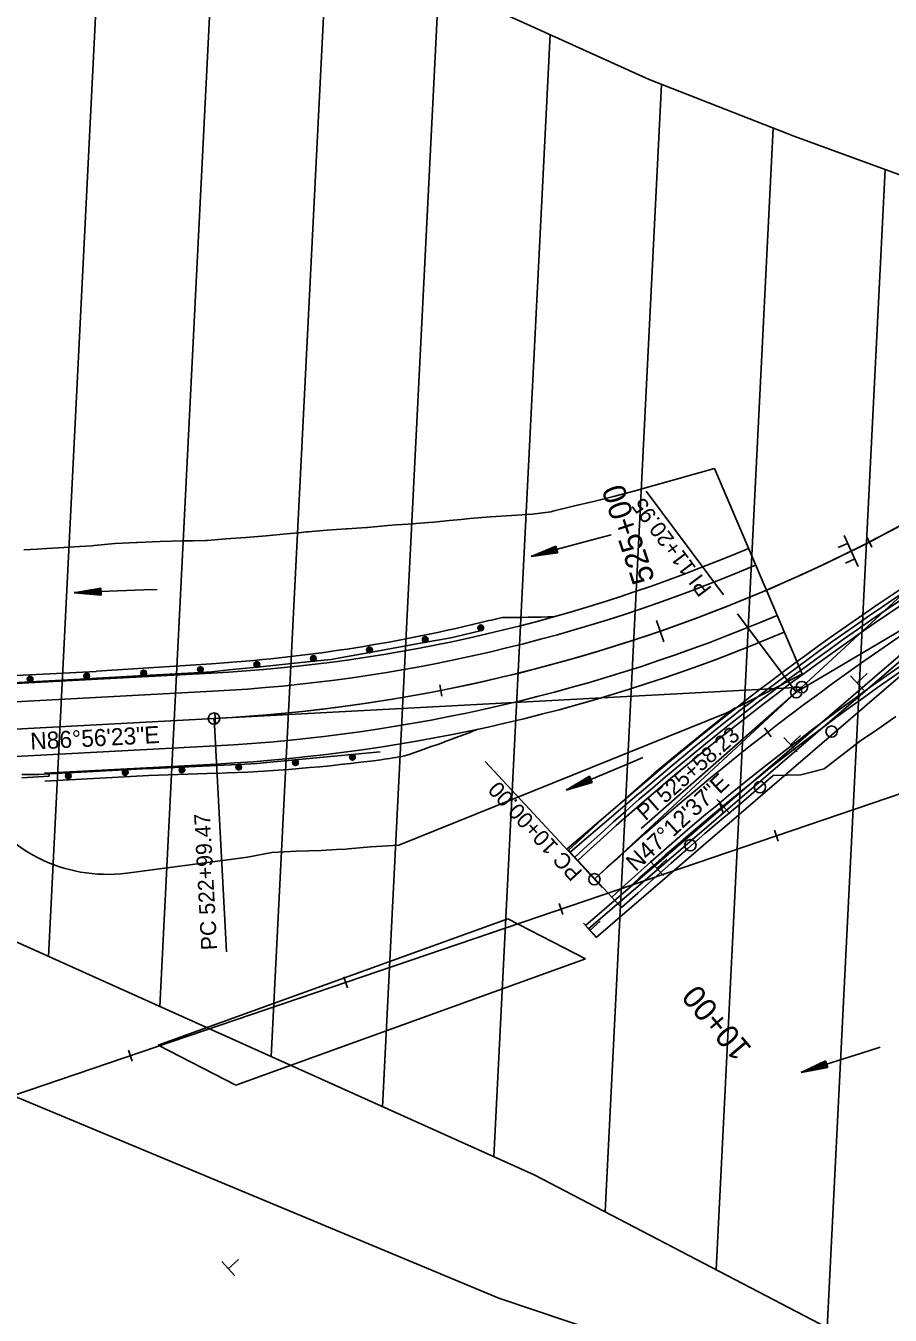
# Model space of a CAD drawing. Extents: x 1300404 to 1323571, y 234004 to 252077.
# Drawn here: x 1310836 to 1311216, y 241590 to 242157 of the extents above; entities that cross this region are included whole.
import ezdxf

# ---------------------------------------------------------------- set-up
doc = ezdxf.new("R2010")
doc.units = 0
for name, color, linetype in [('MOT Stage 1', 7, 'Continuous'), ('R_Barrel', 7, 'Continuous'), ('R_Bridge', 7, 'Continuous'), ('R_BRIDGE OLD', 7, 'Continuous'), ('R_Const Limits', 7, 'Continuous'), ('R_Floodway', 7, 'Continuous'), ('R_Flooplain', 7, 'Continuous'), ('R_Flow Arrows', 7, 'Continuous'), ('R_Guardrail', 7, 'Continuous'), ('R_Horz Alg Annot', 7, 'Continuous'), ('R_Horz Alg Annot Leader', 7, 'Continuous'), ('R_Horz Alg Major Ticks', 7, 'Continuous'), ('R_Horz Alg Minor Ticks', 7, 'Continuous'), ('R_Horz Alg Station Annot', 7, 'Continuous'), ('R_Horz Alg Tangents', 7, 'Continuous'), ('R_Horz Alg Tangents Text', 7, 'Continuous'), ('R_Lane Edge', 7, 'Continuous'), ('R_MOT Proposed', 7, 'Continuous'), ('R_No Plot', 7, 'Continuous'), ('R_Proposed', 7, 'Continuous'), ('R_Shoulder', 7, 'Continuous'), ('R_Temp Widening', 7, 'Continuous')]:
    doc.layers.add(name, color=color, linetype=linetype)

msp = doc.modelspace()

# ---------------------------------------------------------------- linework, layer by layer
at = {"layer": 'MOT Stage 1'}
for p, q in [((1311201.61, 241919.34), (1311195.34, 241932.97)), ((1311196.91, 241929.57), (1311192.82, 241927.69)), ((1311200.04, 241922.75), (1311195.95, 241920.87))]:
    msp.add_line(p, q, dxfattribs=at)
at = {"layer": 'R_Barrel'}
for p, q in [((1311204.01, 241865.09), (1311198.16, 241871.4)), ((1311201.1, 241868.23), (1311205.5, 241872.31)), ((1311174.67, 241837.91), (1311168.82, 241844.22)), ((1311171.76, 241841.05), (1311176.16, 241845.13)), ((1311142.41, 241813.87), (1311146.81, 241817.95)), ((1311145.32, 241810.73), (1311139.47, 241817.04)), ((1311115.97, 241783.55), (1311110.12, 241789.86)), ((1311113.06, 241786.69), (1311117.46, 241790.77)), ((1311086.63, 241756.37), (1311080.78, 241762.68)), ((1311083.72, 241759.51), (1311088.12, 241763.58)), ((1310927.51, 241607.6), (1310921.8, 241614.04)), ((1310924.67, 241610.81), (1310929.16, 241614.78))]:
    msp.add_line(p, q, dxfattribs=at)
at = {"layer": 'R_Bridge'}
for p, q in [((1310841.4, 241827.99), (1310833.89, 241828.01)), ((1310833.97, 241826.59), (1310845.95, 241827.23)), ((1310845.9, 241828.23), (1310841.4, 241827.99)), ((1310845.95, 241827.23), (1310845.9, 241828.23))]:
    msp.add_line(p, q, dxfattribs=at)
at = {"layer": 'R_BRIDGE OLD'}
for p, q in [((1310893.84, 241709.07), (1311047.62, 241764.63)), ((1311047.62, 241764.63), (1311081.7, 241747.01)), ((1310927.92, 241691.44), (1311081.7, 241747.01)), ((1310893.84, 241709.07), (1310927.92, 241691.44))]:
    msp.add_line(p, q, dxfattribs=at)
at = {"layer": 'R_Const Limits'}
for p, q in [((1311176.88, 241872.18), (1311138.36, 241962.48)), ((1311086.31, 241756.33), (1311264.65, 241909.6)), ((1311086.31, 241756.33), (1311081.74, 241761.64))]:
    msp.add_line(p, q, dxfattribs=at)
for points in [[(1310834.85, 241926.68), (1310840.61, 241926.98), (1310844.84, 241927.26), (1310854.81, 241927.93), (1310859.32, 241928.23), (1310864.8, 241928.45), (1310865.67, 241928.55), (1310874.76, 241929.47), (1310884.27, 241929.9), (1310884.75, 241929.92), (1310894.74, 241930.32), (1310904.74, 241930.67), (1310909.26, 241930.74), (1310914.69, 241930.86), (1310915.46, 241930.89), (1310923.57, 241931.5), (1310932.44, 241932.19), (1310941.32, 241932.89), (1310950.19, 241933.75), (1310955.64, 241934.26), (1310959.05, 241934.6), (1310959.83, 241934.67), (1310967.95, 241935.3), (1310976.44, 241935.95), (1310976.86, 241935.99), (1310985.38, 241936.54), (1310985.81, 241936.58), (1310994.75, 241937.37), (1310998.54, 241937.7), (1311003.75, 241937.97), (1311012.75, 241938.72), (1311015.02, 241938.93), (1311021.76, 241939.54), (1311027.06, 241940.05), (1311030.8, 241940.43), (1311036.1, 241941), (1311039.91, 241941.15), (1311049.1, 241941.74), (1311058.31, 241942.46), (1311066.41, 241943.48), (1311067.39, 241943.76), (1311076.26, 241945.88), (1311085.19, 241947.89), (1311094.05, 241950.15), (1311102.88, 241952.57), (1311111.72, 241955.02), (1311120.61, 241957.41), (1311129.48, 241959.91), (1311138.36, 241962.48), (1311138.36, 241962.48)], [(1311176.88, 241872.18), (1311176.88, 241872.18), (1311167.49, 241867.24), (1311158.01, 241862.48), (1311148.53, 241857.62), (1311143.8, 241855.03)], [(1311143.8, 241855.03), (1310999.61, 241796.95)], [(1310999.61, 241796.95), (1310999.61, 241796.95), (1310987.26, 241796.18), (1310977.37, 241795.28), (1310976.42, 241795.2), (1310972.24, 241794.96), (1310965.56, 241794.59), (1310954.67, 241794.33), (1310943.84, 241793.72), (1310933.11, 241791.68), (1310923.25, 241790.38), (1310880.01, 241784.67), (1310880.01, 241784.67)]]:
    msp.add_lwpolyline(points, dxfattribs=at)
msp.add_arc((1310871.29, 241850.65), 66.55, 208.0604, 277.5275, dxfattribs=at)
at = {"layer": 'R_Floodway'}
for p, q in [((1310845.63, 241748), (1310870.89, 242252.19)), ((1310894.59, 241726), (1310919.58, 242224.73)), ((1310943.55, 241703.99), (1310968.37, 242199.27)), ((1310992.51, 241681.98), (1311017.25, 242175.67)), ((1311041.47, 241659.98), (1311066.18, 242153.15)), ((1311090.32, 241635.77), (1311115.15, 242131.3)), ((1311139.11, 241610.32), (1311164.25, 242112.14)), ((1311187.9, 241584.88), (1311213.4, 242093.9))]:
    msp.add_line(p, q, dxfattribs=at)
for points in [[(1312749.18, 241191.87), (1312719.26, 241174.03), (1312375.34, 241167.16), (1311696.89, 241341.68), (1311497.53, 241419.47), (1311333.82, 241508.77), (1311059.08, 241652.06), (1310740.78, 241795.13), (1310453.25, 241924.55), (1310367.2, 241994.21), (1310267.81, 242111.73), (1309996.24, 242391.57), (1309869.69, 242546.75), (1309624.53, 242919.62)], [(1310244.92, 242890.78), (1310303.34, 242800.73), (1310379.63, 242680.75), (1310490.18, 242568.72), (1310548.96, 242534.3), (1310676.05, 242414.18), (1310731.56, 242362.99), (1310810.26, 242291.28), (1310887.62, 242241.41), (1310974.87, 242195.88), (1311031.59, 242168.82), (1311109.67, 242133.43), (1311173.76, 242108.43), (1311242.66, 242083.18), (1311339.33, 242032.34), (1311351.04, 242024.49), (1311431.54, 241940.59), (1311405.15, 241750.77), (1311416.02, 241677.63), (1311441.14, 241598.94), (1311547.83, 241506.46)]]:
    msp.add_lwpolyline(points, dxfattribs=at)
at = {"layer": 'R_Flooplain'}
msp.add_lwpolyline([(1308850.44, 242983.42), (1308921.9, 242863.68), (1309009.78, 242685.04), (1309044.07, 242596.21), (1309055.9, 242542.38), (1309352.07, 242367.77), (1309503.16, 242292.41), (1309669.46, 242230.8), (1309815.49, 242150.85), (1309936.66, 242057.64), (1310419.39, 241839.75), (1310733.16, 241727.16), (1311043.67, 241597.79), (1311103.17, 241577.86), (1311152.77, 241553.58), (1311178, 241525.7), (1311328.48, 241486.66), (1311553.07, 241380.98), (1311870.34, 241289.99), (1312137.52, 241213.62), (1312460.11, 241035.25), (1312721.15, 240884.18), (1312883.23, 240786.49)], dxfattribs=at)
at = {"layer": 'R_Flow Arrows'}
for p, q in [((1311068.69, 241928.4), (1311057.77, 241923.79)), ((1311069.5, 241925.47), (1311057.77, 241923.79)), ((1311069.5, 241925.47), (1311068.69, 241928.4)), ((1310868.58, 241909.89), (1310856.91, 241907.82)), ((1310868.72, 241906.86), (1310868.58, 241909.89)), ((1310868.72, 241906.86), (1310856.91, 241907.82)), ((1311083.45, 241827.21), (1311073.26, 241821.16)), ((1311084.65, 241824.42), (1311073.26, 241821.16)), ((1311084.65, 241824.42), (1311083.45, 241827.21)), ((1311187.21, 241702.12), (1311176.51, 241697.03)), ((1311188.15, 241699.23), (1311176.51, 241697.03)), ((1311188.15, 241699.23), (1311187.21, 241702.12))]:
    msp.add_line(p, q, dxfattribs=at)
for points in [[(1311092.99, 241933.34), (1311087.43, 241931.84), (1311057.74, 241923.93)], [(1311069.01, 241927.22), (1311063.02, 241925.56), (1311059.96, 241924.72)], [(1311069.18, 241926.64), (1311063.19, 241924.98), (1311060.12, 241924.13)], [(1311068.93, 241927.52), (1311062.94, 241925.86), (1311062.14, 241925.64)], [(1311069.26, 241926.35), (1311063.27, 241924.68), (1311062.46, 241924.46)], [(1311068.85, 241927.81), (1311064.32, 241926.55)], [(1311069.34, 241926.05), (1311064.81, 241924.8)], [(1311068.77, 241928.1), (1311066.51, 241927.48)], [(1311069.42, 241925.76), (1311067.16, 241925.13)], [(1310893.37, 241909.32), (1310887.61, 241909.09), (1310856.9, 241907.97)], [(1310868.63, 241908.68), (1310862.42, 241908.39), (1310859.24, 241908.25)], [(1310868.66, 241908.07), (1310862.45, 241907.78), (1310859.27, 241907.64)], [(1310868.62, 241908.98), (1310862.41, 241908.69), (1310861.58, 241908.65)], [(1310868.6, 241909.29), (1310863.91, 241909.07)], [(1310868.59, 241909.59), (1310866.24, 241909.48)], [(1310868.68, 241907.77), (1310862.46, 241907.48), (1310861.63, 241907.44)], [(1310868.69, 241907.46), (1310863.99, 241907.24)], [(1310868.7, 241907.16), (1310866.36, 241907.05)], [(1311106.85, 241835.41), (1311101.54, 241833.17), (1311073.2, 241821.3)], [(1311083.93, 241826.09), (1311078.22, 241823.63), (1311075.29, 241822.38)], [(1311084.17, 241825.53), (1311078.46, 241823.07), (1311075.53, 241821.82)], [(1311083.81, 241826.37), (1311078.1, 241823.91), (1311077.33, 241823.58)], [(1311084.29, 241825.25), (1311078.58, 241822.79), (1311077.81, 241822.46)], [(1311083.69, 241826.65), (1311079.37, 241824.79)], [(1311084.41, 241824.98), (1311080.09, 241823.11)], [(1311083.57, 241826.93), (1311081.41, 241826)], [(1311084.53, 241824.7), (1311082.37, 241823.77)], [(1311211.27, 241708.14), (1311205.77, 241706.39), (1311176.46, 241697.17)], [(1311187.58, 241700.96), (1311181.67, 241699.04), (1311178.65, 241698.06)], [(1311187.77, 241700.39), (1311181.86, 241698.46), (1311178.83, 241697.48)], [(1311187.49, 241701.25), (1311181.58, 241699.33), (1311180.79, 241699.07)], [(1311187.87, 241700.1), (1311181.95, 241698.17), (1311181.16, 241697.91)], [(1311187.39, 241701.54), (1311182.93, 241700.08)], [(1311187.96, 241699.81), (1311183.49, 241698.35)], [(1311187.3, 241701.83), (1311185.07, 241701.1)], [(1311188.05, 241699.52), (1311185.82, 241698.79)]]:
    msp.add_lwpolyline(points, dxfattribs=at)
at = {"layer": 'R_Guardrail'}
for p, q in [((1311036.38, 241891.45), (1311034.42, 241892.42)), ((1311011.98, 241886.29), (1311010.01, 241887.25)), ((1310987.47, 241881.74), (1310985.5, 241882.7)), ((1310913.11, 241873.04), (1310911.14, 241874.01)), ((1310937.94, 241875.32), (1310935.97, 241876.29)), ((1310962.78, 241877.96), (1310960.81, 241878.93)), ((1310838.28, 241868.8), (1310836.32, 241869.77)), ((1310863.15, 241870.24), (1310861.18, 241871.21)), ((1310888.19, 241871.56), (1310886.22, 241872.53)), ((1310979.96, 241834.54), (1310977.99, 241835.51)), ((1310880.1, 241827.78), (1310878.14, 241828.75)), ((1310905.03, 241829.04), (1310903.06, 241830)), ((1310929.97, 241830.25), (1310928, 241831.21)), ((1310954.92, 241832.17), (1310952.95, 241833.14)), ((1310855.07, 241826.39), (1310853.11, 241827.36))]:
    msp.add_line(p, q, dxfattribs=at)
for points in [[(1311023.77, 241888.41), (1311035.95, 241891.24)], [(1311036.73, 241891.83), (1311034.51, 241892.92)], [(1311035.67, 241891.21), (1311034.66, 241891.71)], [(1311036.89, 241892.31), (1311034.79, 241893.34)], [(1311036.85, 241892.87), (1311035.26, 241893.66)], [(1311035.95, 241891.24), (1311036.51, 241891.37)], [(1310986.89, 241881.64), (1311011.49, 241886.09)], [(1311012.33, 241886.67), (1311010.1, 241887.76)], [(1311011.27, 241886.04), (1311010.25, 241886.54)], [(1311012.48, 241887.14), (1311010.39, 241888.17)], [(1311012.44, 241887.71), (1311010.86, 241888.49)], [(1311011.49, 241886.09), (1311021.72, 241887.94), (1311023.77, 241888.41)], [(1310963.28, 241878.82), (1310961.19, 241879.85)], [(1310963.25, 241879.39), (1310961.66, 241880.17)], [(1310974.59, 241879.41), (1310986.89, 241881.64)], [(1310987.81, 241882.12), (1310985.59, 241883.21)], [(1310986.76, 241881.49), (1310985.74, 241881.99)], [(1310987.97, 241882.59), (1310985.88, 241883.62)], [(1310987.93, 241883.16), (1310986.35, 241883.94)], [(1310913.45, 241873.43), (1310911.23, 241874.52)], [(1310913.61, 241873.9), (1310911.51, 241874.93)], [(1310913.57, 241874.47), (1310911.99, 241875.25)], [(1310912.46, 241872.85), (1310917.47, 241873.14), (1310924.91, 241873.91)], [(1310924.91, 241873.91), (1310937.34, 241875.19)], [(1310938.28, 241875.7), (1310936.06, 241876.79)], [(1310937.23, 241875.08), (1310936.21, 241875.58)], [(1310938.44, 241876.18), (1310936.35, 241877.21)], [(1310938.4, 241876.74), (1310936.82, 241877.53)], [(1310937.34, 241875.19), (1310962.21, 241877.76)], [(1310963.13, 241878.35), (1310960.9, 241879.44)], [(1310962.07, 241877.72), (1310961.06, 241878.22)], [(1310962.21, 241877.76), (1310969.88, 241878.56), (1310974.59, 241879.41)], [(1310825.09, 241868.03), (1310837.57, 241868.7)], [(1310838.63, 241869.18), (1310836.41, 241870.28)], [(1310837.57, 241868.56), (1310836.56, 241869.06)], [(1310838.78, 241869.66), (1310836.69, 241870.69)], [(1310838.75, 241870.23), (1310837.16, 241871.01)], [(1310837.57, 241868.7), (1310862.54, 241870.03)], [(1310863.5, 241870.63), (1310861.28, 241871.72)], [(1310862.44, 241870), (1310861.43, 241870.5)], [(1310863.65, 241871.1), (1310861.56, 241872.13)], [(1310863.62, 241871.67), (1310862.03, 241872.45)], [(1310862.54, 241870.03), (1310866.78, 241870.26), (1310875.02, 241870.73)], [(1310875.02, 241870.73), (1310887.5, 241871.44)], [(1310888.53, 241871.95), (1310886.31, 241873.04)], [(1310887.48, 241871.32), (1310886.46, 241871.82)], [(1310888.69, 241872.42), (1310886.59, 241873.45)], [(1310888.65, 241872.99), (1310887.06, 241873.77)], [(1310887.5, 241871.44), (1310912.46, 241872.85)], [(1310912.4, 241872.8), (1310911.38, 241873.3)], [(1310954.11, 241834.41), (1310941.66, 241833.23)], [(1310955.39, 241833.59), (1310953.8, 241834.38)], [(1310978.99, 241836.78), (1310954.11, 241834.41)], [(1310980.3, 241834.92), (1310978.08, 241836.02)], [(1310979.25, 241834.3), (1310978.23, 241834.8)], [(1310980.46, 241835.4), (1310978.36, 241836.43)], [(1310980.42, 241835.97), (1310978.84, 241836.75)], [(1310991.44, 241837.97), (1310978.99, 241836.78)], [(1310854.28, 241828.68), (1310845.9, 241828.23)], [(1310855.54, 241827.82), (1310853.95, 241828.6)], [(1310879.25, 241830.01), (1310854.28, 241828.68)], [(1310880.45, 241828.16), (1310878.23, 241829.26)], [(1310880.61, 241828.64), (1310878.51, 241829.67)], [(1310880.57, 241829.21), (1310878.98, 241829.99)], [(1310891.73, 241830.67), (1310889.6, 241830.57), (1310889.58, 241830.57), (1310879.25, 241830.01)], [(1310904.22, 241831.27), (1310891.73, 241830.67)], [(1310905.37, 241829.42), (1310903.15, 241830.51)], [(1310904.32, 241828.79), (1310903.3, 241829.29)], [(1310905.53, 241829.89), (1310903.44, 241830.92)], [(1310905.49, 241830.46), (1310903.91, 241831.24)], [(1310929.19, 241832.44), (1310919.51, 241832), (1310904.22, 241831.27)], [(1310930.32, 241830.63), (1310928.09, 241831.72)], [(1310929.26, 241830), (1310928.24, 241830.5)], [(1310930.47, 241831.1), (1310928.38, 241832.13)], [(1310930.43, 241831.67), (1310928.85, 241832.45)], [(1310941.66, 241833.23), (1310937.35, 241832.82), (1310929.19, 241832.44)], [(1310955.27, 241832.55), (1310953.05, 241833.64)], [(1310954.21, 241831.93), (1310953.2, 241832.43)], [(1310955.42, 241833.03), (1310953.33, 241834.06)], [(1310855.42, 241826.77), (1310853.2, 241827.87)], [(1310854.37, 241826.15), (1310853.35, 241826.65)], [(1310855.58, 241827.25), (1310853.48, 241828.28)], [(1310879.4, 241827.54), (1310878.38, 241828.04)]]:
    msp.add_lwpolyline(points, dxfattribs=at)
for centre in [(1311035.67, 241892.47), (1311011.26, 241887.31), (1310962.06, 241878.99), (1310986.75, 241882.76), (1310912.39, 241874.07), (1310937.22, 241876.34), (1310837.57, 241869.83), (1310862.43, 241871.27), (1310887.47, 241872.59), (1310954.2, 241833.19), (1310979.24, 241835.56), (1310854.36, 241827.42), (1310879.39, 241828.8), (1310904.31, 241830.06), (1310929.25, 241831.27)]:
    msp.add_circle(centre, 1.25, dxfattribs=at)
at = {"layer": 'R_Horz Alg Annot Leader'}
for points in [[(1311176.79, 241866.37), (1311106.14, 241804.2)], [(1311176.79, 241866.37), (1311106.14, 241804.2)], [(1310918.4, 241852.55), (1310923.88, 241750.03)], [(1310918.4, 241852.55), (1310923.88, 241750.03)]]:
    msp.add_lwpolyline(points, dxfattribs=at)
at = {"layer": 'R_Horz Alg Major Ticks'}
msp.add_lwpolyline([(1311112.91, 241895.7), (1311116.18, 241886.25)], dxfattribs=at)
msp.add_lwpolyline([(1311112.91, 241895.7), (1311116.18, 241886.25)], dxfattribs=at)
at = {"layer": 'R_Horz Alg Minor Ticks'}
for points in [[(1311205.31, 241932.4), (1311207.59, 241927.95)], [(1311205.31, 241932.4), (1311207.59, 241927.95)], [(1311017.6, 241867.39), (1311018.56, 241862.48)], [(1311017.6, 241867.39), (1311018.56, 241862.48)], [(1310918.79, 241855.08), (1310919.06, 241850.09)], [(1310918.79, 241855.08), (1310919.06, 241850.09)], [(1311164.81, 241803.47), (1311166.43, 241798.74)], [(1311164.81, 241803.47), (1311166.43, 241798.74)], [(1311070.15, 241771.25), (1311071.76, 241766.52)], [(1311070.15, 241771.25), (1311071.76, 241766.52)], [(1310975.48, 241739.02), (1310977.09, 241734.29)], [(1310975.48, 241739.02), (1310977.09, 241734.29)], [(1310880.82, 241706.8), (1310882.43, 241702.07)], [(1310880.82, 241706.8), (1310882.43, 241702.07)]]:
    msp.add_lwpolyline(points, dxfattribs=at)
at = {"layer": 'R_Horz Alg Tangents'}
for p, q in [((1311176.79, 241866.37), (1311366.68, 242042.15)), ((1311176.79, 241866.37), (1311366.68, 242042.15)), ((1310918.4, 241852.55), (1311176.79, 241866.37)), ((1310918.4, 241852.55), (1311176.79, 241866.37))]:
    msp.add_line(p, q, dxfattribs=at)
at = {"layer": 'R_Lane Edge'}
for p, q in [((1310472.71, 241840.74), (1310917.76, 241864.54)), ((1310533.26, 241819.95), (1310919.04, 241840.57))]:
    msp.add_line(p, q, dxfattribs=at)
for radius in [704.2, 728.2]:
    msp.add_arc((1310880.16, 242567.73), radius, 273.06037, 293.10284, dxfattribs=at)
at = {"layer": 'R_MOT Proposed'}
for p, q in [((1311174.35, 241864.11), (1311278.31, 241925.93)), ((1311085.59, 241781.94), (1311174.35, 241864.11))]:
    msp.add_line(p, q, dxfattribs=at)
for points in [[(1311142.37, 241906.91), (1311108.3, 241952.5)], [(1311174.35, 241864.11), (1311148.56, 241898.62)], [(1311160.31, 241848.56), (1311163.37, 241844.61)], [(1311085.59, 241781.94), (1311037.61, 241833.77)], [(1311082.19, 241785.61), (1311088.98, 241778.27)]]:
    msp.add_lwpolyline(points, dxfattribs=at)
for centre in [(1311174.35, 241864.11), (1311085.59, 241781.94)]:
    msp.add_circle(centre, 2.5, dxfattribs=at)
msp.add_arc((1311864.02, 240941.01), 1145.92, 120.73904, 132.78965, dxfattribs=at)
at = {"layer": 'R_No Plot'}
for p, q in [((1311103.85, 241821.08), (1311073.6, 241795.35)), ((1311105.21, 241819.61), (1311074.95, 241793.89)), ((1311140.42, 241816.28), (1311142.25, 241811))]:
    msp.add_line(p, q, dxfattribs=at)
msp.add_lwpolyline([(1311218.17, 241853.52), (1311210.21, 241847.87), (1311202.11, 241842.43), (1311194.35, 241836.51), (1311186.65, 241830.52), (1311176.34, 241827.89), (1311164.14, 241827.53), (1311156.65, 241821.12), (1311149.2, 241814.66), (1311141.57, 241808.43), (1311134.11, 241802), (1311126.7, 241795.51), (1311119.33, 241788.97), (1311111.95, 241782.46), (1311104.63, 241775.87), (1311097.52, 241769.5), (1311096.63, 241770.46), (1311094.64, 241772.61), (1311093.28, 241774.08), (1311085.81, 241782.15), (1311078.34, 241790.23), (1311076.98, 241791.69), (1311074.99, 241793.84), (1311074.18, 241794.72), (1311081.42, 241801.38), (1311088.92, 241808.23), (1311096.47, 241815.01), (1311104.05, 241821.76), (1311111.68, 241828.45), (1311119.5, 241834.93), (1311127.38, 241841.34), (1311135.28, 241847.71), (1311143.21, 241854.04), (1311147.39, 241857.35)], dxfattribs=at)
for centre in [(1311189.87, 241846.83), (1311158.38, 241822.4), (1311127.77, 241796.88)]:
    msp.add_circle(centre, 2.5, dxfattribs=at)
for radius, start, end in [(1158.92, 120.73904, 132.7743), (1162.92, 120.73904, 130.81889), (1160.92, 120.73904, 130.8155), (1156.92, 120.73904, 132.7743), (1134.92, 120.36636, 132.7743), (1132.92, 120.73904, 132.7743)]:
    msp.add_arc((1311864.02, 240941.01), radius, start, end, dxfattribs=at)
at = {"layer": 'R_Proposed'}
for p, q in [((1310715.59, 241647.91), (1311574.84, 241940.41)), ((1310715.59, 241647.91), (1311574.84, 241940.41)), ((1310473.35, 241828.76), (1310918.4, 241852.55)), ((1310473.35, 241828.76), (1310918.4, 241852.55))]:
    msp.add_line(p, q, dxfattribs=at)
for centre in [(1311176.79, 241866.37), (1311176.79, 241866.37), (1310918.4, 241852.55), (1310918.4, 241852.55)]:
    msp.add_circle(centre, 2.5, dxfattribs=at)
for centre, radius, start, end in [((1310880.16, 242567.73), 716.2, 273.06037, 312.78965), ((1310880.16, 242567.73), 716.2, 273.06037, 312.78965), ((1310880.16, 242567.73), 716.2, 273.06037, 312.78965), ((1310880.16, 242567.73), 716.2, 273.06037, 312.78965), ((1310880.16, 242567.73), 716.2, 274.98457, 312.78965), ((1310880.16, 242567.73), 716.2, 274.98457, 312.78965), ((1310880.16, 242567.73), 716.2, 274.98457, 312.78965), ((1310880.16, 242567.73), 716.2, 274.98457, 312.78965), ((1310737.29, 241372.32), 231.5, 311.1667, 114.4738), ((1310737.29, 241372.32), 231.5, 311.1667, 114.4738)]:
    msp.add_arc(centre, radius, start, end, dxfattribs=at)
at = {"layer": 'R_Shoulder'}
for p, q in [((1310917.24, 241876.63), (1310866.75, 241873.34)), ((1310814.05, 241870.51), (1310866.62, 241873.32)), ((1310814.23, 241867.01), (1310917.33, 241872.53)), ((1310814.23, 241867.01), (1310866.8, 241869.82)), ((1310843.88, 241828.54), (1310919.47, 241832.58)), ((1310844.06, 241825.05), (1310889.75, 241827.49)), ((1310889.7, 241827.49), (1310919.63, 241828.5))]:
    msp.add_line(p, q, dxfattribs=at)
for centre, radius, start, end in [((1310880.16, 242567.73), 696.2, 273.06037, 293.10284), ((1310880.16, 242567.73), 690.7, 283.01244, 283.81244), ((1311045.8, 242611.29), 714.28, 269.94055, 271.78055), ((1310872.29, 242565.86), 690.7, 273.73154, 283.68361), ((1310880.16, 242567.73), 736.2, 273.06037, 293.10284), ((1310762.89, 242545.39), 748.52, 288.63889, 291.27888), ((1310894.5, 242569.77), 741.7, 271.9418, 277.54588), ((1310880.16, 242567.73), 741.7, 278.66444, 279.46444)]:
    msp.add_arc(centre, radius, start, end, dxfattribs=at)
at = {"layer": 'R_Temp Widening'}
for p, q in [((1311081.74, 241761.64), (1311260.09, 241914.9)), ((1311083.05, 241760.12), (1311261.39, 241913.39))]:
    msp.add_line(p, q, dxfattribs=at)

# ---------------------------------------------------------------- texts
at = {"layer": 'R_Horz Alg Annot'}
for s, rotation, p in [('PI 525+58.23', 41.345, (1311108.05, 241807.39)), ('PI 525+58.23', 41.345, (1311108.05, 241807.39)), ('PC 522+99.47', 93.0604, (1310919.82, 241750.97)), ('PC 522+99.47', 93.0604, (1310919.82, 241750.97))]:
    msp.add_text(s, height=7, rotation=rotation, dxfattribs=at).set_placement(p)
at = {"layer": 'R_Horz Alg Station Annot'}
msp.add_text('525+00', height=10, rotation=108.3472, dxfattribs=at).set_placement((1311112.32, 241913.63))
at = {"layer": 'R_Horz Alg Tangents Text'}
msp.add_text('N86%%d56\'23"E', height=7.5, rotation=3.0604, dxfattribs=at).set_placement((1310837.82, 241838.83))
msp.add_text('N86%%d56\'23"E', height=7.5, rotation=3.0604, dxfattribs=at).set_placement((1310837.82, 241838.83))
at = {"layer": 'R_MOT Proposed'}
for s, height, rotation, p in [('PI 11+20.95', 7, 126.7643, (1311137.46, 241909.61)), ('N47%%d12\'37"E', 7.5, 42.7896, (1311103.76, 241784.98)), ('PC 10+00.00', 7, 132.7896, (1311080.77, 241785.27)), ('10+00', 10, 130.0969, (1311155.19, 241707.63))]:
    msp.add_text(s, height=height, rotation=rotation, dxfattribs=at).set_placement(p)

doc.saveas('drawing.dxf')
